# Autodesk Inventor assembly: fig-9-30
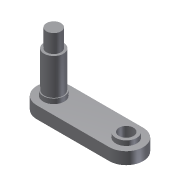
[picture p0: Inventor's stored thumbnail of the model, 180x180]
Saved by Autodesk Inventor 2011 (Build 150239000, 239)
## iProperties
Shininess: 64.0
Length Units: 11269
Angle Units: 11279
Time Units: 11290
Mass Units: 11283
Length Display Precision: 3
Angle Display Precision: 2
Created: 2002-01
Part Number: fig-9-30
Document SubType Name: Assembly
Designer: ***
Density: 0.0
Volumn: 0.0
Area: 0.0
PropertySet Name: Model Information
Control State: 0
Master: False
Checked Out: False
Author: ***
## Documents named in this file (3)
- C:\Users\CADSoft\Desktop\part files\c09-inv-2011-prt\fig-9-30.iam
- C:\Users\CADSoft\Desktop\inventor\c09-inv-2010-prt\c09\Part5.ipt
- C:\Users\CADSoft\Desktop\inventor\c09-inv-2010-prt\c09\Part6.ipt
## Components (2 placed, 2 different names)
1. Part5:1 — Insert:1
2. Part6:1 — Insert:1
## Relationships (1: Insert 1)
- Insert:1: Part5:1 ↔ Part6:1
